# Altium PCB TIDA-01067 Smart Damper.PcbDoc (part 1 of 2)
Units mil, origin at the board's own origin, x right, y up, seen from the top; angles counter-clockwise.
Board outline 4000 x 3450 mil, 4 copper layers (Top Layer, Signal Layer 1, Signal Layer 2, Bottom Layer), stack 63 mil thick; 101 components, 44 nets, 285 pads, 617 vias.
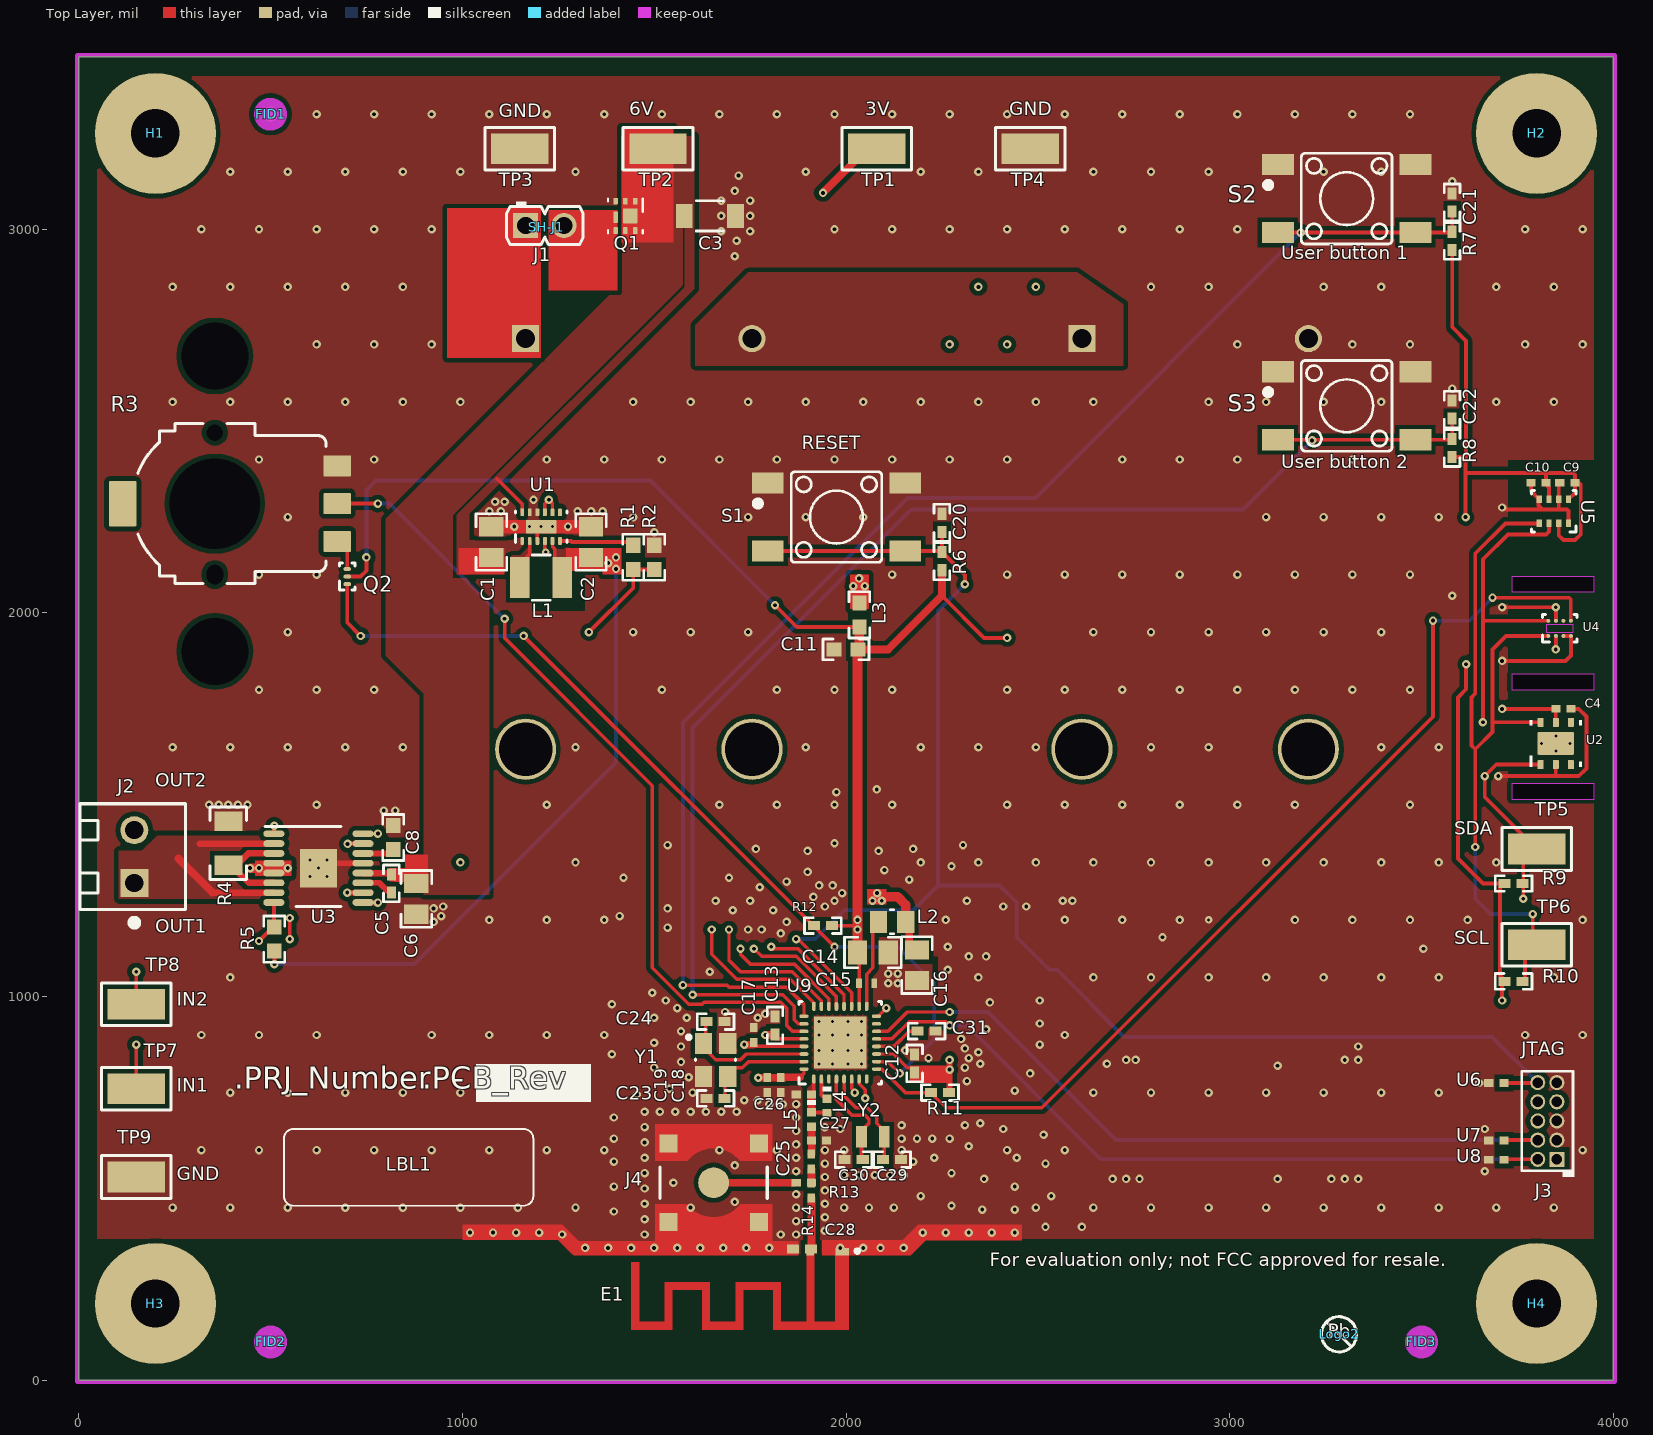
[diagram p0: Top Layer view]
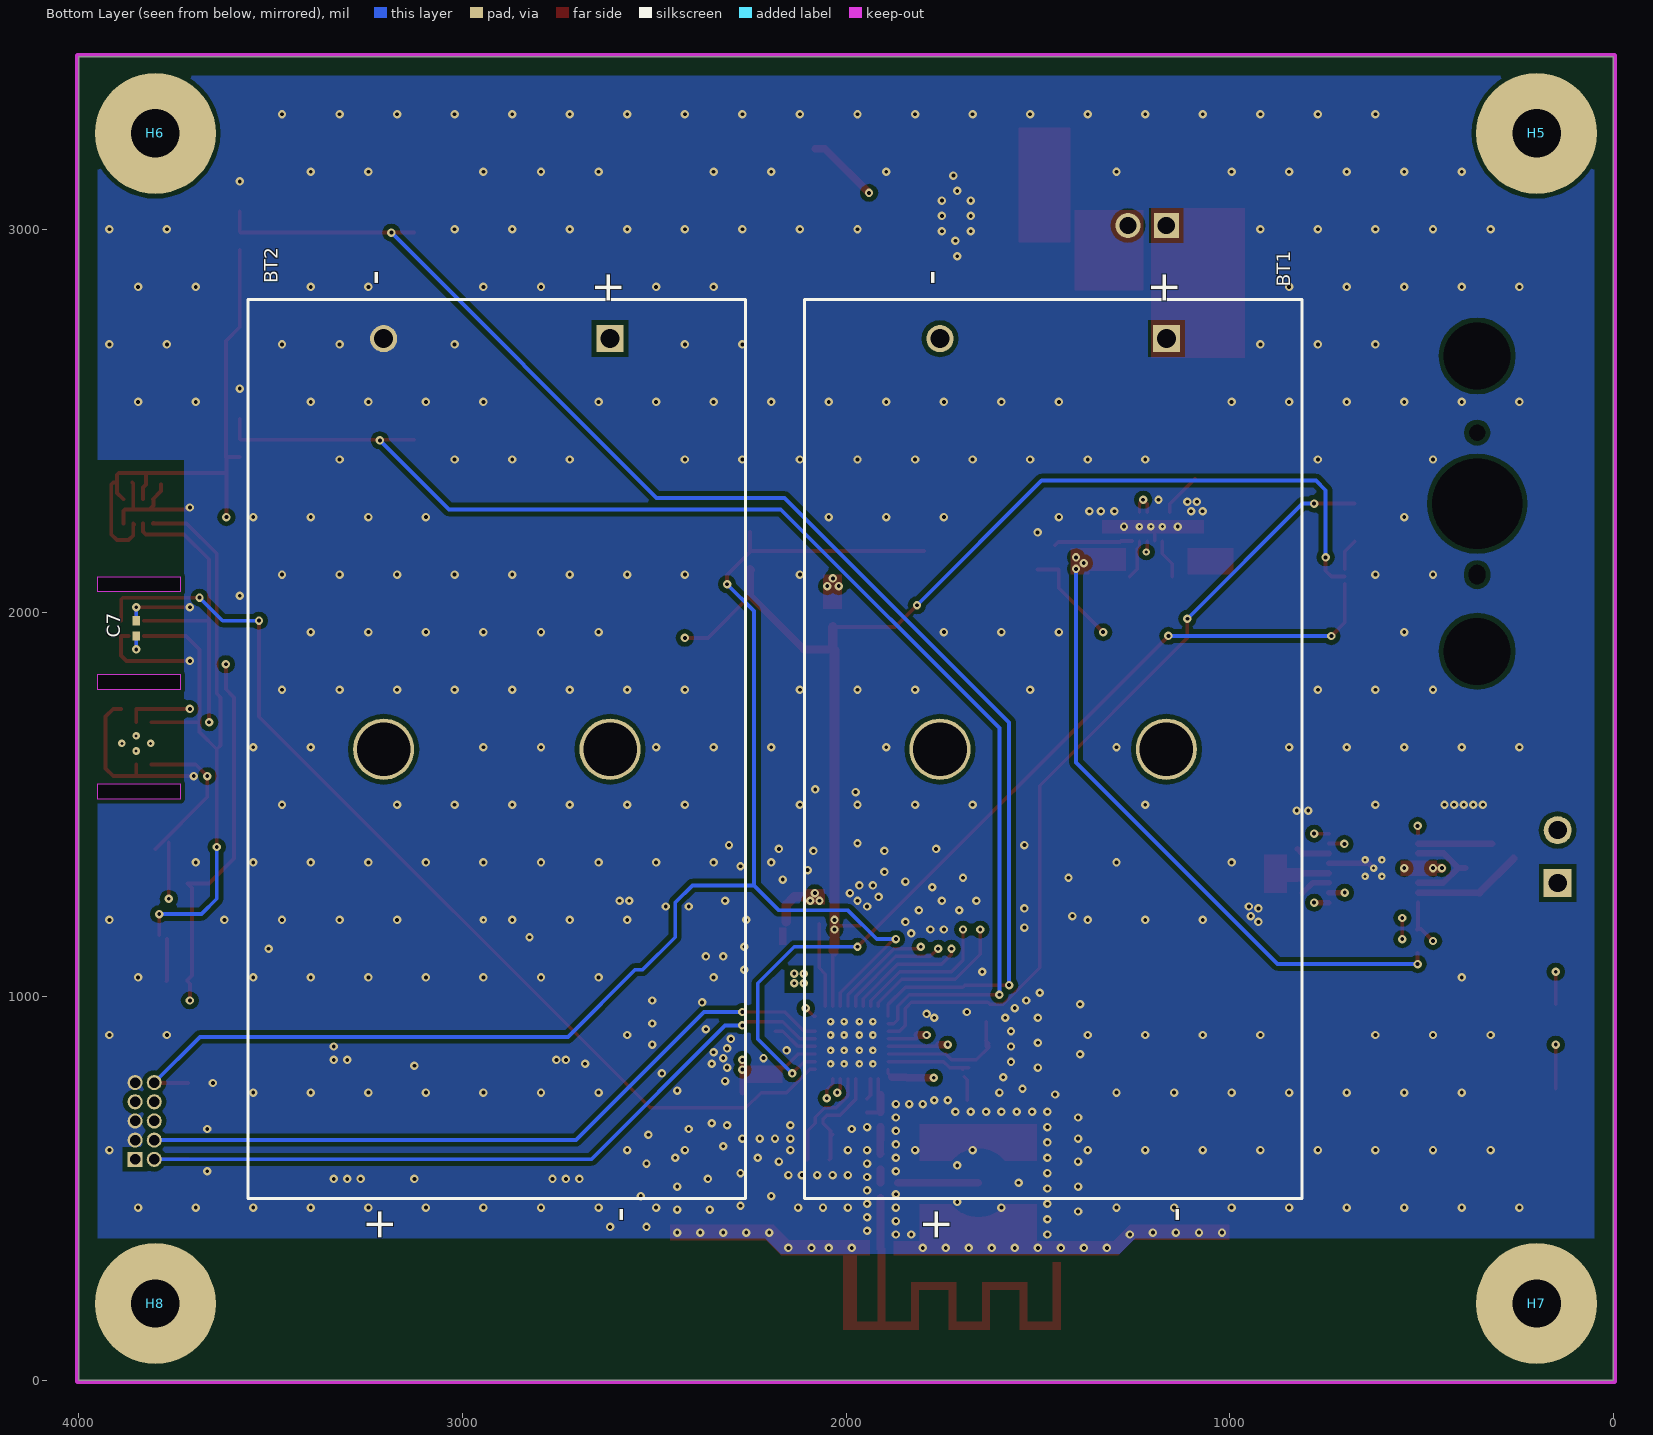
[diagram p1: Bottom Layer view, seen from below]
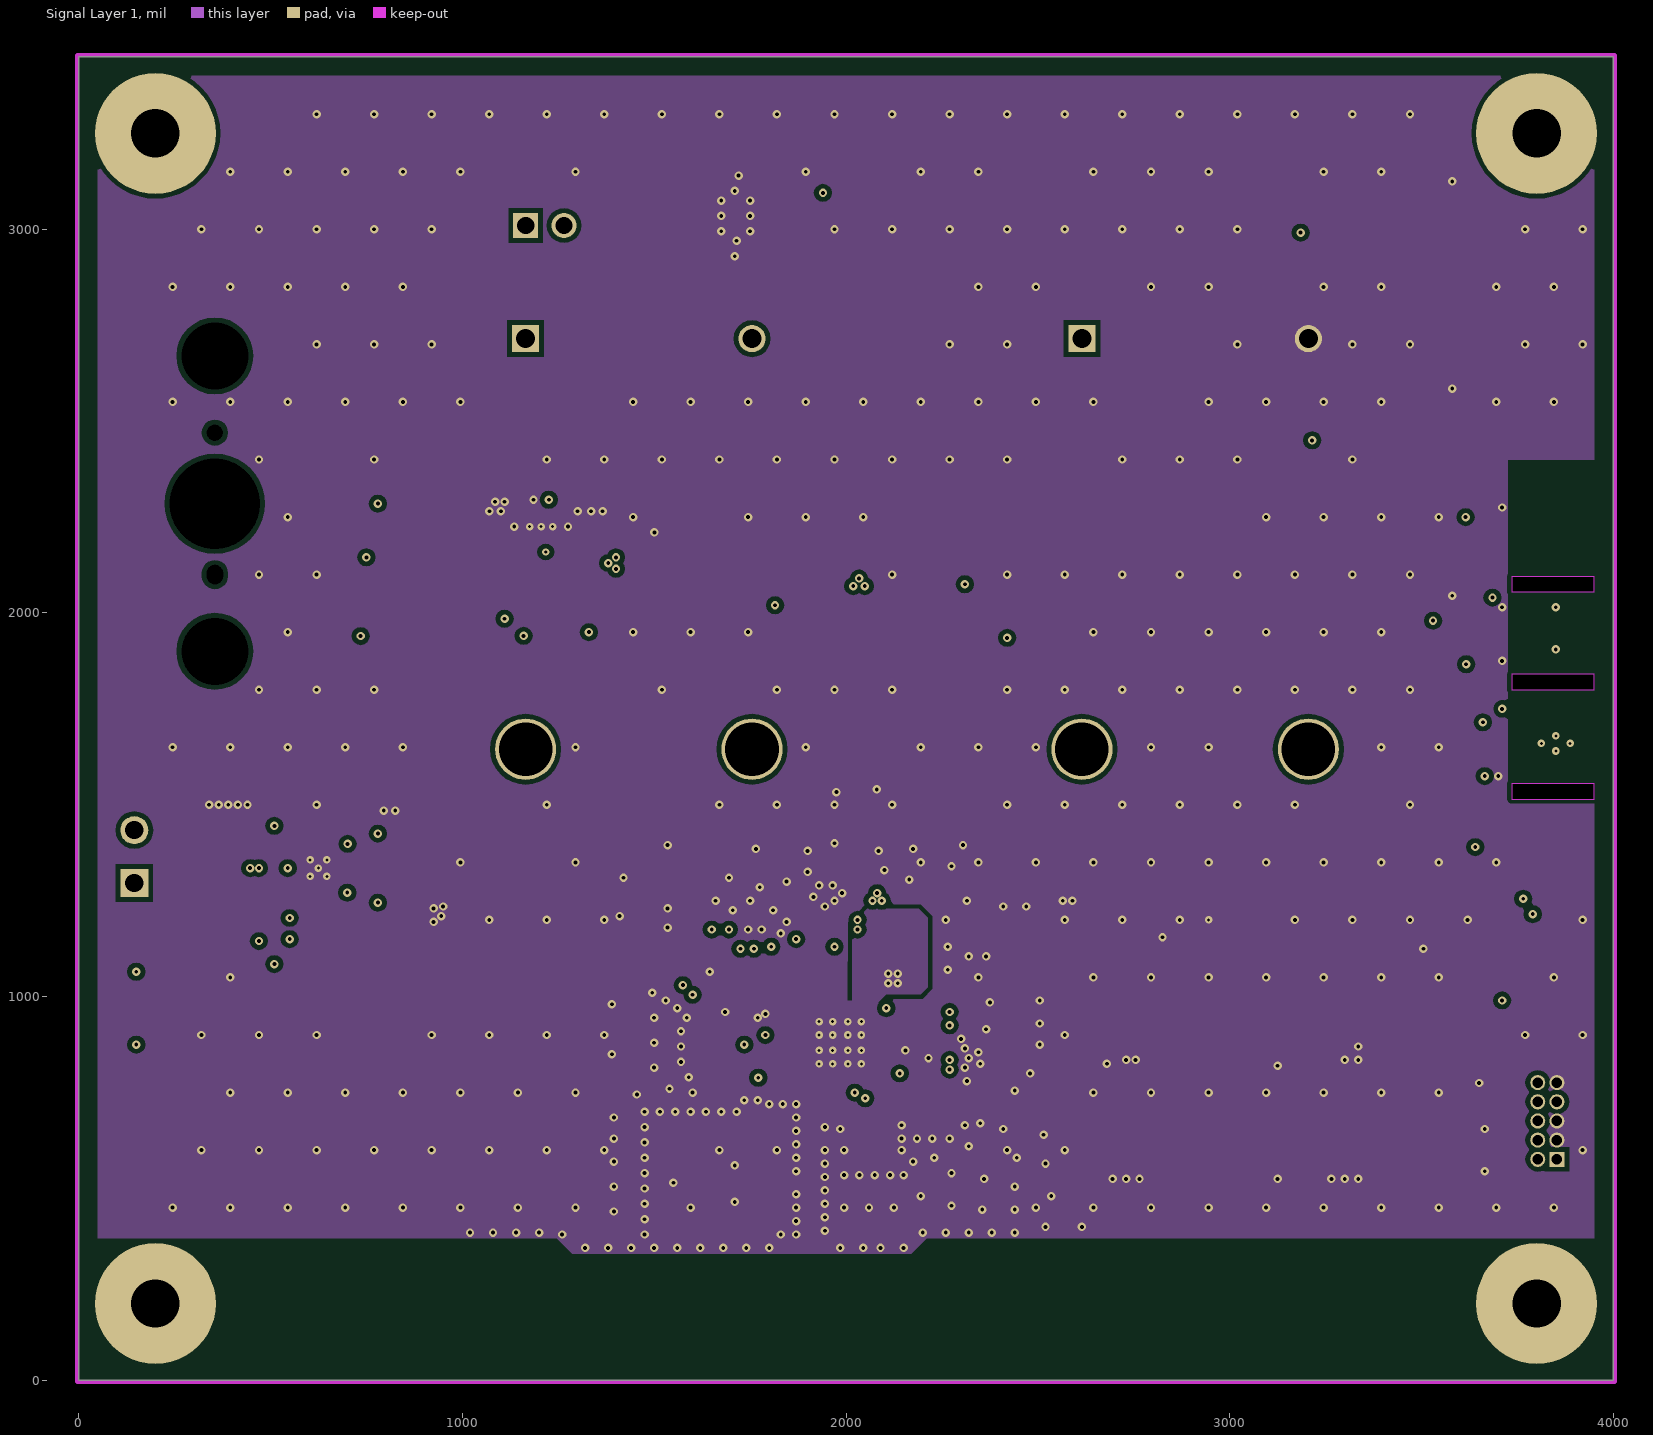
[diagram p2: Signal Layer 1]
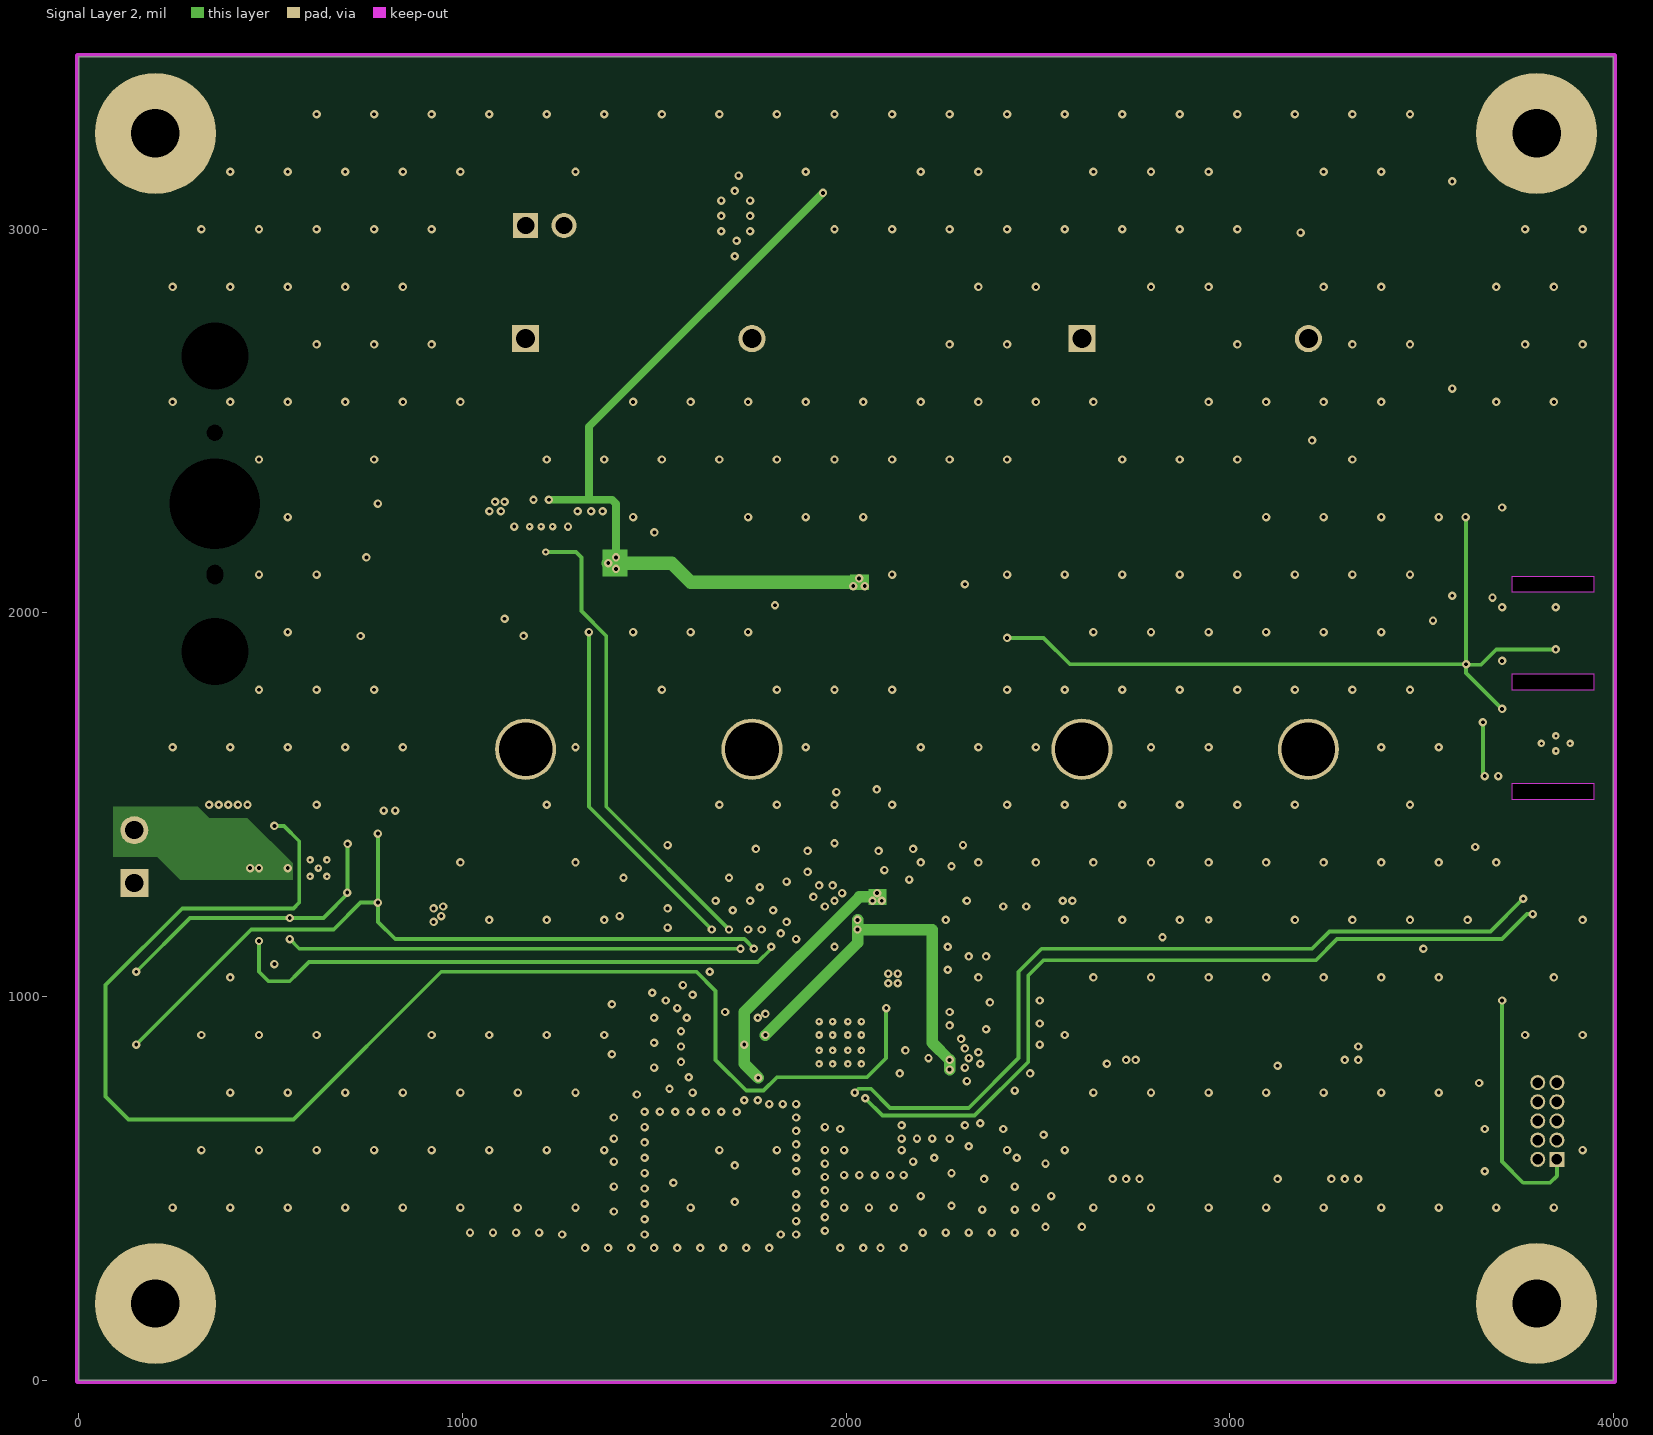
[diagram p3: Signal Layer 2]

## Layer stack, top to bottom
Top Solder: solder mask 0.4, Solder Resist, Dk 3.5
Top Layer: signal copper 1.4
Dielectric1: core 6.9, FR-4 High TG, Dk 4.2
Signal Layer 1: signal copper 0.7
Dielectric 2: prepreg 45, FR-4 High TG, Dk 4.2
Signal Layer 2: signal copper 0.7
Dielectric 3: core 6.9, FR-4 High TG, Dk 4.2
Bottom Layer: signal copper 1.4
Bottom Solder: solder mask 0.4, Solder Resist, Dk 3.5

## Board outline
0,0 0,3450 4000,3450 4000,0
cut-out: 3735,2095 3735,2055 3950,2055 3950,2095
cut-out: 3735,1840 3735,1800 3950,1800 3950,1840
cut-out: 3735,1555 3735,1515 3950,1515 3950,1555

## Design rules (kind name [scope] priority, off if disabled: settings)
AcuteAngle [All] p1: minimum=4.50000000000000E+0001 checktracksonly=FALSE
AssemblyTestPointUsage [All] p1: valid=2
Clearance Clearance_Keepouts [((IsTrack Or IsArc) And Not InPoly) And IsFree and IsKeepOut vs ((IsTrack Or IsArc) And Not InPoly) And IsFree and IsKeepOut] p1: gap=0
Clearance Clearance_Poly [InPolygon] p2: gap=12
Clearance [All] p3: gap=7.87
ComponentClearance ComponentClearance_RF [InComponent('C33') OR InComponent('E1') OR InComponent('R15') OR InComponent('R14')] p1: gap=0 collisioncheckmode=3 verticalgap=0 showdistances=FALSE
ComponentClearance ComponentClearance_MountingHoles_FiducialMarks [InComponentClass('Mounting Holes') vs InComponentClass('FiducialMark')] p2: gap=50 collisioncheckmode=3 verticalgap=10 showdistances=FALSE
ComponentClearance ComponentClearance_Shunt [InComponentClass('Header') vs InComponentClass('Shunt')] p3: gap=0 collisioncheckmode=3 verticalgap=0 showdistances=FALSE
ComponentClearance ComponentClearance_Logo [InComponentClass('Logo')] p4: gap=0 collisioncheckmode=3 verticalgap=0 showdistances=FALSE
ComponentClearance ComponentClearance_ScrewToNut [(HasFootprint('NY PMS 440 0025 PH')) vs (HasFootprint('Keystone_1902E'))] p5: gap=5 collisioncheckmode=3 verticalgap=10 showdistances=FALSE
ComponentClearance ComponentClearance_MountingHoles [InComponentClass('Mounting Holes')] p6: gap=50 collisioncheckmode=3 verticalgap=100000 showdistances=FALSE
ComponentClearance ComponentClearance_SmallPassives [HasFootprint('0201*') or HasFootprint('0402*') or HasFootprint('0508') or HasFootprint('0603*') or HasFootprint('0612') or HasFootprint('0805*') or HasFootprint('0815*') or HasFootprint('0830*') or HasFootprint('1206*') or HasFootprint('1210*') or HasFootprint('1808*') or HasFootprint('1812*') or HasFootprint('1825*') or HasFootprint('2010*') or HasFootprint('2220*') or HasFootprint('2225*') or HasFootprint('2512*') or HasFootprint('2728*') or HasFootprint('3518*') vs HasFootprint('0201*') or HasFootprint('0402*') or HasFootprint('0508') or HasFootprint('0603*') or HasFootprint('0612') or HasFootprint('0805*') or HasFootprint('0815*') or HasFootprint('0830*') or HasFootprint('1206*') or HasFootprint('1210*') or HasFootprint('1808*') or HasFootprint('1812*') or HasFootprint('1825*') or HasFootprint('2010*') or HasFootprint('2220*') or HasFootprint('2225*') or HasFootprint('2512*') or HasFootprint('2728*') or HasFootprint('3518*')] p7: gap=10 collisioncheckmode=3 verticalgap=10 showdistances=FALSE
ComponentClearance ComponentClearance_THtoSMT [IsThruComponent vs IsSMTComponent] p8: gap=40 collisioncheckmode=3 verticalgap=30 showdistances=FALSE
ComponentClearance ComponentClearance_THtoTH [IsThruComponent vs IsThruComponent] p9: gap=30 collisioncheckmode=3 verticalgap=30 showdistances=FALSE
ComponentClearance [All] p10: gap=15 collisioncheckmode=3 verticalgap=10 showdistances=FALSE
DiffPairsRouting [All] p1: maxlimit=100 minlimit=10 mostfreqgap=10 toplayer_minwidth=15 toplayer_maxwidth=15 toplayer_prefwidth=15 midlayer1_minwidth=15 midlayer1_maxwidth=15 midlayer1_prefwidth=15 midlayer2_minwidth=15 midlayer2_maxwidth=15 midlayer2_prefwidth=15 bottomlayer_minwidth=15 bottomlayer_maxwidth=15 bottomlayer_prefwidth=15 maxuncoupledlength=1000
FabricationTestPointUsage TestPointUsage [All] p1: valid=2 allowmultiple=FALSE
FabricationTestpoint Testpoint [All] p1: side=3 testpointundercomponent=TRUE minsize=40 maxsize=100 preferedsize=60 minholesize=0 maxholesize=40 preferedholesize=32 testpointgrid=1 allowsidetop=TRUE allowsidebottom=TRUE usegrid=TRUE gridtolerance=0.01
FanoutControl Fanout_LCC [IsLCC] p1: bgadir=Out bgaviamode=Centered fanoutstyle=Auto fanoutdirection=Alternating viagrid=1 // Fanout_LCC (Default Rule)
FanoutControl Fanout_BGA [IsBGA] p2: bgadir=Out bgaviamode=Centered fanoutstyle=Auto fanoutdirection=Alternating viagrid=1 // Fanout_BGA (Default Rule)
FanoutControl Fanout_Default [All] p4: bgadir=Out bgaviamode=Centered fanoutstyle=Auto fanoutdirection=Alternating viagrid=1 // Fanout_Default (Default Rule)
FanoutControl Fanout_Small [(CompPinCount < 5)] p5: bgadir=Out bgaviamode=Centered fanoutstyle=Auto fanoutdirection=OutThenIn viagrid=1 // Fanout_Small (Default Rule)
Height [All] p1: minheight=0 maxheight=1100 prefheight=500
HoleSize [All] p1: absolutevalues=TRUE maxlimit=251 minlimit=7.87 maxpercent=80.000 minpercent=20.000
MinimumAnnularRing MinimumAnnularRing_ThermalPadVias [IsVia and InAnyComponent] p1: minimumring=5.91
MinimumAnnularRing [All] p2: minimumring=5.5
MinimumSolderMaskSliver MinimumSolderMaskSliver_Logo [InComponentClass('Logo') vs InComponentClass('Logo')] p1: minsoldermaskwidth=0.7
MinimumSolderMaskSliver [All] p2: minsoldermaskwidth=3.94
PlaneConnect [All] p1: planeconnectstyle=Relief reliefexpansion=10 reliefentries=4 reliefconductorwidth=10 reliefairgap=10
PolygonConnect [All] p1: connectstyle=Direct reliefconductorwidth=10 reliefentries=4 polygonreliefangle="90 Angle" airgapwidth=10
RoutingVias ThermalPadVias [IsVia and InAnyComponent] p1: holewidth=7.87 width=19.68 viastyle="Through Hole" minholewidth=7.87 minwidth=19.68 maxholewidth=12.99 maxwidth=23.62
RoutingVias [All] p2: holewidth=10 width=34 viastyle="Through Hole" minholewidth=7.87 minwidth=19 maxholewidth=40 maxwidth=65
SilkToBoardRegionClearance [Not ((IsComment or IsDesignator) And (Hide <> 'False')) and not InRegion(1000,500,4000,800)] p1 off:
SilkToSilkClearance SilkToSilkClearance_Pb-FreeLogo [(HasFootprint('Pb-Free_Overlay_Medium') OR HasFootprint('Pb-Free_Overlay_Small')) vs (HasFootprint('Pb-Free_Overlay_Medium') OR HasFootprint('Pb-Free_Overlay_Small'))] p1: silktosilkclearance=0
SilkToSilkClearance [All] p2: silktosilkclearance=3
SilkToSolderMaskClearance SilkToComponentPadClearance [IsPad and InAnycomponent] p1: minsilkscreentomaskgap=3 clearancetoexposedcopper=TRUE
SilkToSolderMaskClearance "Silk to Solder Mask Opening" [All] p2: minsilkscreentomaskgap=3 clearancetoexposedcopper=FALSE
SolderMaskExpansion [All] p1: expansion=1.97
Width [All] p1: maxlimit=100 minlimit=7.8 preferedwidth=10 checkconnectedcopper=TRUE
14 further rules are at their usual default settings.

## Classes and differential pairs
component class "Mounting Holes": H1 H2 H3 H4
component class "TIDA-01067 Smart Damper_Hardware": FID1 FID2 FID3 H1 H2 H3 H4 H5 H6 H7 H8 LBL1 Logo2 Logo3 SH-J1 ZZ1 ZZ2 ZZ3 ZZ4
component class FiducialMark: FID1 FID2 FID3
component class AssemblyNote: ZZ1 ZZ2 ZZ3 ZZ4
component class Label: LBL1
component class Header: J1 J3
component class "TIDA-01067 Smart Damper_Sheet1": BT1 BT2 C1 C2 C3 C4 C5 C6 C7 C8 C9 C10 J1 J2 L1 Q1 Q2 R1 R2 R3 R4 R5 TP1 TP2 TP3 TP4 U1 U2 U3 U4 U5
component class "TIDA-01067 Smart Damper_Sheet2": C11 C12 C13 C14 C15 C16 C17 C18 C19 C20 C21 C22 C23 C24 C25 C26 C27 C28 C29 C30 C31 E1 J3 J4 L2 L3 L4 L5 R6 R7 R8 R9 R10 R11 R12 R13 R14 S1 S2 S3 TP5 TP6 TP7 TP8 TP9 U6 U7 U8 U9 Y1 Y2
component class Shunt: SH-J1

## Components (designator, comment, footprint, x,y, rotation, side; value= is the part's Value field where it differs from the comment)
BT1 "2462" Keystone_2462 1460,2180 r270 bottom locked
BT2 "2462" Keystone_2462 2910,2180 r270 bottom locked
C1 "EMK212BB7106MG-T" 0805_HV 1075.45,2185 r270 top
C2 "EMK212BB7106MG-T" 0805_HV 1335.45,2185 r270 top
C3 "C3216X5R1A107M160AC" 1206_190 1645,3035 r180 top
C4 "GRM155R71A104KA01D" 0402L 3870,1750 r180 top
C5 "C1005X7R1C103K050BA" 0402 815,1295 r90 top
C6 "EMK212BB7106MG-T" 0805_HV 880,1255 r90 top
C7 "GRM155R71A104KA01D" 0402L 3850,1960 r270 bottom
C8 "C0603C225K9PACTU" 0603 820,1415 r90 top
C9 "GRM155R71A104KA01D" 0402L 3880,2340 r0 top
C10 "GRM155R71A104KA01D" 0402L 3805,2340 r0 top
C11 "C1608X5R1A106M080AC" 0603 2000,1905 r180 top
C12 "GRM155R71A104KA01D" 0402 2179,826 r270 top
C13 "GRM155R71A104KA01D" 0402 1815,925 r270 top
C14 "GRM21BR71A106KE51L" 0805_HV 2070,1115 r0 top
C15 "GRM155R71A104KA01D" 0402S 2053.9,1035 r180 top
C16 "GRM21BR71A106KE51L" 0805_HV 2185,1082 r270 top
C17 "GRM155R71A104KA01D" 0402L 1760,900 r270 top
C18 "GRM155R71A104KA01D" 0402L 1830,770 r90 top
C19 "885012205037" 0402L 1795,770 r270 top
C20 "C1005X7R1H222K" 0402 2250,2235 r270 top
C21 "C1005X7R1H222K" 0402 3580,3070 r270 top
C22 "C1005X7R1H222K" 0402 3580,2530 r270 top
C23 "GRM1555C1H120JA01D" 0402 1660,735 r0 top
C24 "GRM1555C1H120JA01D" 0402 1660,935 r180 top
C25 "GRM1555C1H120JA01D" 0402L 1910,570 r90 top
C26 "GRM1555C1H1R2CA01D" 0402L 1890,745 r180 top
C27 "GRM1555C1H1R2CA01D" 0402L 1930,625 r0 top
C28 "GRM1555C1H1R2CA01D" 0402 1885,342 r0 top
C29 "GRM1555C1H120JA01D" 0402 2120,575 r180 top
C30 "GRM1555C1H120JA01D" 0402 2020,575 r180 top
C31 "GRM155R61A105KE15D" 0402 2210,910 r180 top
E1 "ANTENNA_IIFA" ANTENNA_IIFA 1990,345 r180 top net-tie
FID1 "Fiducial" Fiducial10-20 500,3300 r0 top
FID2 "Fiducial" Fiducial10-20 500,100 r0 top
FID3 "Fiducial" Fiducial10-20 3500,100 r0 top
H1 "NY PMS 440 0025 PH" "NY PMS 440 0025 PH" 200,3250 r0 top locked
H2 "NY PMS 440 0025 PH" "NY PMS 440 0025 PH" 3800,3250 r0 top locked
H3 "NY PMS 440 0025 PH" "NY PMS 440 0025 PH" 200,200 r0 top locked
H4 "NY PMS 440 0025 PH" "NY PMS 440 0025 PH" 3800,200 r0 top locked
H5 "1902E" Keystone_1902E 200,3250 r180 bottom locked
H6 "1902E" Keystone_1902E 3800,3250 r180 bottom locked
H7 "1902E" Keystone_1902E 200,200 r180 bottom locked
H8 "1902E" Keystone_1902E 3800,200 r180 bottom locked
J1 "61300211121" WURTH_61300211121 1215,3010 r0 top
J2 "OSTTE020161" On-Shore_OSTTE020161 145,1365 r90 top
J3 "GRPB052VWVN-RC" CONN_GRPB052VWVN-RC 3828,676 r90 top
J4 "CONSMA001-SMD-G" Linx_CONSMA001-SMD-G 1655,515 r90 top
L1 "CBC3225T4R7MR" CBC3225 1205.45,2092 r0 top
L2 "CKS2125100M-T" 0805_145 2120,1195 r0 top
L3 "BLM18HE152SN1D" 0603 2035,1995 r270 top
L4 "LQG15HS15NJ02D" IND_LQG15H 1950,715 r270 top
L5 "LQG15HS2N0S02D" IND_LQG15H 1910,680 r270 top
LBL1 "Size: 0.65\" x 0.20 \"" Label_650x200 860,555 r0 top
Logo2 "Pb-Free Symbol" Pb-Free_Overlay_Small 3285,120 r0 top
Logo3 "FCC disclaimer" FCC_disclaimer 1010,-460 r270 top
Q1 "CSD25310Q2" TRANS_NexFET_Q2 1425,3035 r270 top
Q2 "CSD23285F5" YJK0003A 700,2095 r90 top
R1 "RC0603FR-0738K3L" 0603 1445.45,2145 r90 top
R2 "ERJ-3EKF3002V" 0603 1500.45,2145 r90 top
R3 "EVW-AE4001B14" Panasonic_EVW-AE4001B14 355,2285 r180 top
R4 "CSR1206FKR100" 1206 390,1400 r270 top
R5 "ERJ-3EKF1001V" 0603 510,1150 r270 top
R6 "CRCW040247K5FKED" 0402 2250,2135 r270 top
R7 "CRCW040247K5FKED" 0402 3580,2970 r270 top
R8 "CRCW040247K5FKED" 0402 3580,2430 r270 top
R9 "CRCW040210K0FKED" 0402 3740,1295 r180 top
R10 "CRCW040210K0FKED" 0402 3740,1040 r180 top
R11 "CRCW040210K0FKED" 0402 2245,750 r0 top
R12 "CRCW040210K0FKED" 0402 1940,1185 r0 top
R13 "CRCW04021K00JNED" 0402L 1890,515 r180 top
R14 "ERJ-2GE0R00X" 0402L 1910,495 r270 top
S1 "4-1437565-1" SW_FSM4JSMA 1975,2250 r90 top
S2 "4-1437565-1" SW_FSM4JSMA 3305,3080 r90 top
S3 "4-1437565-1" SW_FSM4JSMA 3305,2540 r90 top
SH-J1 "969102-0000-DA" SNT-100-BK-G 1220,3005 r180 top
TP1 "TESTPOINT" Keystone_5019 2080,3210 r0 top
TP2 "TESTPOINT" Keystone_5019 1510,3210 r0 top
TP3 "TESTPOINT" Keystone_5019 1150,3210 r0 top
TP4 "TESTPOINT" Keystone_5019 2480,3210 r0 top
TP5 "TESTPOINT" Keystone_5019 3800,1385 r0 top
TP6 "TESTPOINT" Keystone_5019 3800,1135 r0 top
TP7 "TESTPOINT" Keystone_5019 150,760 r0 top
TP8 "TESTPOINT" Keystone_5019 150,980 r180 top
TP9 "TESTPOINT" Keystone_5019 150,530 r0 top
U1 "TPS62745DSSR" DSS0012A 1205.45,2225 r90 top
U2 "HDC1080DMBR" DMB0006A 3850,1660 r90 top
U3 "DRV8833PWPR" PWP0016C_N 625,1335 r0 top
U4 "HDC1010YPAR" YPA0008AGAE 3860,1960 r90 top
U5 "BMP280" LGA8-2X2_5MM_0_65 3845,2265 r180 top
U6 "TPD1E10B06DPYR" DPY0002A 3695,775 r180 top
U7 "TPD1E10B06DPYR" DPY0002A 3695,625 r180 top
U8 "TPD1E10B06DPYR" DPY0002A 3695,575 r180 top
U9 "CC2650F128RHBR" RHB0032E 1985,880 r90 top locked
Y1 "TSX-3225 24.0000MF20G-AC3" EPSON_TSX-3225 1660,835 r0 top
Y2 "FC-12M 32.7680KA-A3" Epson_FC-12M 2070,635 r0 top
ZZ1 "This Assembly Note is for PCB labels only" AssemblyNoteLabel 185,3915 r0 top
ZZ2 "These assemblies are ESD sensitive, ESD precautions shall be observed." AssemblyNote 185,3829.11 r0 top
ZZ3 "These assemblies must be clean and free from flux and all contaminants. Use of no clean flux is not acceptable." AssemblyNote 185,3740.56 r0 top
ZZ4 "These assemblies must comply with workmanship standards IPC-A-610 Class 2, unless otherwise specified." AssemblyNote 185,3652 r0 top

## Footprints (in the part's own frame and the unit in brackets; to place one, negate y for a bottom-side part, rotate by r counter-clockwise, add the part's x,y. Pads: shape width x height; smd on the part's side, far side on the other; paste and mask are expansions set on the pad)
0402 [mm] "0402 from SM-752 data"
  rect 0.8x0.6 smd: 1(-0.6,0) 2(0.6,0)
  silkscreen extent -1.22,-0.52 1.22,0.52, body extent -0.55,-0.3 0.55,0.3, height 0.6
0402L [mm] "0402 from SM-752 data"
  rect 0.6x0.5 smd: 1(-0.5,0) 2(0.5,0)
  body extent -0.55,-0.3 0.55,0.3, height 0.6
0402S [mil] "Based on C0402S footprint from PADS legacy"
  rect 15x24 smd: 1(-20,0) 2(20,0)
  body extent -22,-12 22,12, height 24
0603 [mm] "0603 from SM-752 data"
  rect 1x0.95 smd: 1(-0.8,0) 2(0.8,0)
  silkscreen extent -1.52,-0.69 1.52,0.69, body extent -0.87,-0.47 0.87,0.47, height 1
0805_145 [mm] "0805 / 1.45mm height"
  rect 1.15x1.45 smd: 1(-0.9,0) 2(0.9,0)
  silkscreen extent -0.1,-0.8 0.1,0.8, body extent -1.1,-0.72 1.1,0.72, height 1.45
0805_HV [mil] "0805 with 30mil clearance between pads"
  rect 50x63 smd: 1(-40,0) 2(40,0)
  silkscreen extent -74,-40 74,40, body extent -43,-29 43,29, height 57
1206 [mm] "1206 from SM-752 data"
  rect 1.3x1.85 smd: 1(-1.45,0) 2(1.45,0)
  silkscreen extent -2.4,-1.21 2.4,1.21, body extent -1.7,-0.9 1.7,0.9, height 1.35
1206_190 [mm] "1206_190"
  rect 1.1x1.6 smd: 1(-1.7,0) 2(1.7,0)
  silkscreen extent -0.9,-1 0.9,1, body extent -1.75,-0.95 1.75,0.95, height 1.9
ANTENNA_IIFA [mm] "PCB Antenna, 2-Leads"
  rect 0.9x0.5 smd paste-1 mask-1: 1(0,0.25)
  rect 0.5x0.5 smd paste-1 mask-1: 2(2.1,0.25)
  Top Layer region: -0.45,0 -0.45,5.4 4.55,5.4 4.55,2.76 6.55,2.76 6.55,5.4 9.25,5.4 9.25,2.76 11.25,2.76 11.25,5.4 13.95,5.4 13.95,0.96 13.45,0.96 13.45,4.9 11.75,4.9 11.75,2.26 8.75,2.26 8.75,4.9 7.05,4.9 7.05,2.26 4.05,2.26 4.05,4.9 2.35,4.9 2.35,0 1.85,0 1.85,4.9 0.45,4.9 0.45,0
  silkscreen extent -1.1,0.11 -0.9,0.31
AssemblyNote [mil] "Assembly Note"
AssemblyNoteLabel [mil] "Assembly Note for PCB Labels"
CBC3225 [mm] "TAIYO YUDEN, IPC nominal footprint."
  rect 1.29x2.72 smd: 1(-1.405,0) 2(1.405,0)
  silkscreen extent -0.6,-1.5 0.6,1.5, body extent -1.7,-1.35 1.7,1.35, height 2.7
CONN_GRPB052VWVN-RC [mm] "SULLINS"
  rect 1x1 hole 0.7 mask+0.08: 1(-2.54,-0.635)
  round 1 hole 0.7 mask+0.08: 2(-2.54,0.635) 3(-1.27,-0.635) 4(-1.27,0.635) 5(0,-0.635) 6(0,0.635) 7(1.27,-0.635) 8(1.27,0.635) 9(2.54,-0.635) 10(2.54,0.635)
  silkscreen extent -3.7,-1.8 3.3,1.7, body extent -3.17,-1.7 3.17,1.7, height 4
DMB0006A [mm] "TI"
  rrect25% 0.6x0.4 smd: 1(-1.4,1) 2(-1.4,0) 3(-1.4,-1) 4(1.4,-1) 5(1.4,0) 6(1.4,1)
  rrect9% 1.38x1.06 on Top Paste: 7(0,0.63) 7(0,-0.63)
  rrect7% 1.5x2.4 smd paste-0.75: 7(0,0)
  silkscreen extent -1.55,-1.75 1.55,1.75, body extent -1.5,-1.5 1.5,1.5, height 0.81
DPY0002A [mm] "R-PX2SON-N2"
  rect 0.6x0.5 smd: 1(-0.5,0) 2(0.5,0)
  body extent -0.55,-0.35 0.55,0.35, height 0.4
DSS0012A [mm] "SON, 12-Leads, Body 2x3mm, Pitch 0.5mm, Thermal Pad 2x0.9mm, TI Recommended"
  rrect40% 0.5x0.25 smd: 1(-0.95,1.25) 2(-0.95,0.75) 3(-0.95,0.25) 4(-0.95,-0.25) 5(-0.95,-0.75) 6(-0.95,-1.25) 7(0.95,-1.25) 8(0.95,-0.75) 9(0.95,-0.25) 10(0.95,0.25) 11(0.95,0.75) 12(0.95,1.25)
  rrect11% 0.9x0.9 on Top Paste: 13(0,0.55) 13(0,-0.55)
  rrect11% 0.9x2 smd paste-0.45: 13(0,0)
  silkscreen extent -1.05,-1.7 1.05,1.7, body extent -1,-1.5 1,1.5, height 0.81
Epson_FC-12M [mm] "Epson"
  rect 0.7x1.4 smd: 1(-0.75,0) 2(0.75,0)
  body extent -1.05,-0.63 1.05,0.63, height 0.6
EPSON_TSX-3225 [mm] "SMD, 4-Leads, Body 2.65x3.35mm, Height 0.6mm"
  rect 1.15x1.4 smd: 1(-0.8,1.1) 2(-0.8,-1.1) 3(0.8,-1.1) 4(0.8,1.1)
  silkscreen extent -1.9,-0.05 1.33,1.62, body extent -1.33,-1.68 1.33,1.68, height 0.61
FCC_disclaimer [mil]
Fiducial10-20 [mm]
  round 1 smd mask+0.5: 1(0,0)
  Top Layer keep-out circle w1.178: c0,0 r0.5
IND_LQG15H [mm] "MuRata"
  rect 0.55x0.6 smd: 1(-0.475,0) 2(0.475,0)
  silkscreen extent -1.3,-0.3 -0.95,0.3, body extent -0.52,-0.27 0.52,0.27, height 0.55
Keystone_1902E [mil] "Hex Standoff, 4-40 threaded, nylon"
  round 1 on Mech4: 0(0,0)
  body extent -145,-126 146,126, height 1001
Keystone_2462 [mm] "2x AA Battery Holder, Through-hole mount"
  rect 1.8x1.8 hole 1.27: 1(-13.59,7.495)
  round 1.8 hole 1.27: 2(-13.59,-7.495)
  round 4.05 hole 3.55: 3(13.59,-7.495) 4(13.59,7.495)
  silkscreen extent -16.18,-16.46 43.33,16.46, body extent -16.31,-16.46 43.4,16.46, height 16
Keystone_5019 [mm] "Test Point, Miniature, SMT"
  rect 3.8x2.03 smd: 1(0,0)
  silkscreen extent -2.31,-1.42 2.31,1.42, body extent -1.9,-1.02 1.9,1.02, height 2.29
Label_650x200 [mil] "Thermal Transfer Label"
  silkscreen extent -325,-100 325,100, body extent -325,-100 325,100, height 1
LGA8-2X2_5MM_0_65 [mm] "LGA, 8-Leads, Body 2x2.5mm, Pitch 0.65mm"
  rect 0.35x0.5 smd: 1(-0.975,0.8) 2(-0.325,0.8) 3(0.325,0.8) 4(0.975,0.8) 5(0.975,-0.8) 6(0.325,-0.8) 7(-0.325,-0.8) 8(-0.975,-0.8)
  silkscreen extent -1.47,-1.36 1.47,1.36, body extent -1.3,-1.05 1.3,1.05, height 1.01
Linx_CONSMA001-SMD-G [mm] "SMD, 5-Leads, Body 7x7mm, Height 10.5mm"
  round 2.05 smd: 1(0,0)
  rect 1.2x1.2 smd: 2(-2.6,-3) 3(2.6,-3) 4(2.6,3) 5(-2.6,3)
  Top Layer region: -3.88,-3.88 -1.44,-3.88 -1.44,-1.761 -1.448,-1.761 -2.062,-0.974 -2.28,0 -2.062,0.974 -1.448,1.761 -1.448,1.761 -1.44,1.761 -1.44,3.88 -3.88,3.88
  Top Layer region: 3.88,-3.88 1.44,-3.88 1.44,-1.761 1.448,-1.761 2.062,-0.974 2.28,0 2.062,0.974 1.448,1.761 1.448,1.761 1.44,1.761 1.44,3.88 3.88,3.88
  silkscreen extent -1.04,-3.55 1.04,3.55, body extent -3.55,-3.55 3.55,3.55, height 10.5
"NY PMS 440 0025 PH" [mm] "4-40 nylon screw and mounting hole"
  round 8 hole 3.2: 1(0,0)
  body extent -3.3,-3.3 3.3,3.3, height 2.69
On-Shore_OSTTE020161 [mm] "Term Blk 2x1"
  rect 1.85x1.85 hole 1.2: 1(-1.75,0)
  round 1.85 hole 1.2: 2(1.75,0)
  silkscreen extent -4.47,-3.4 3.5,3.6, body extent -3.5,-3.4 3.5,3.6, height 8.4
Panasonic_EVW-AE4001B14 [mm] "SMD, 4-Leads, Body 10.6x12.65mm"
  rrect7% 1.8x1.4 smd: 1(-8.1,2.5) 2(-8.1,0) 3(-8.1,-2.5)
  rrect6% 1.8x3 smd: 4(6.1,0)
  round 0 hole 1.1 slot 1.3 at 90 deg unplated: ""(0,4.7)
  round 0 hole 6 unplated: ""(0,0)
  round 0 hole 1.1 unplated: ""(0,-4.7)
  silkscreen extent -7.35,-5.3 5.1,5.3, body extent -8.7,-5.3 6.7,5.3, height 2.2
Pb-Free_Overlay_Small [mil]
  silkscreen extent -46,-46 46,46
PWP0016C_N [mm] "SOP, 16-Leads, Body 5x4.4mm, Pitch 0.65mm, Thermal Pad 2.56x2.46mm, IPC Medium Density"
  rrect100% 1.4x0.45 smd: 1(-2.95,2.275) 2(-2.95,1.625) 3(-2.95,0.975) 4(-2.95,0.325) 5(-2.95,-0.325) 6(-2.95,-0.975) 7(-2.95,-1.625) 8(-2.95,-2.275) 9(2.95,-2.275) 10(2.95,-1.625) 11(2.95,-0.975) 12(2.95,-0.325) 13(2.95,0.325) 14(2.95,0.975) 15(2.95,1.625) 16(2.95,2.275)
  rrect4% 2.46x2.56 smd: 17(0,0)
  silkscreen extent -3.55,-2.55 1.5,2.75, body extent -3.21,-2.5 3.21,2.5, height 1
RHB0032E [mm] "QFN, 32-Leads, Body 5x5mm, Pitch 0.5mm, Thermal Pad 3.45x3.45mm, TI Recommended"
  oval 0.6x0.24 smd: 1(-2.4,1.75) 2(-2.4,1.25) 3(-2.4,0.75) 4(-2.4,0.25) 5(-2.4,-0.25) 6(-2.4,-0.75) 7(-2.4,-1.25) 8(-2.4,-1.75) 17(2.4,-1.75) 18(2.4,-1.25) 19(2.4,-0.75) 20(2.4,-0.25) 21(2.4,0.25) 22(2.4,0.75) 23(2.4,1.25) 24(2.4,1.75)
  oval 0.24x0.6 smd: 9(-1.75,-2.4) 10(-1.25,-2.4) 11(-0.75,-2.4) 12(-0.25,-2.4) 13(0.25,-2.4) 14(0.75,-2.4) 15(1.25,-2.4) 16(1.75,-2.4) 25(1.75,2.4) 26(1.25,2.4) 27(0.75,2.4) 28(0.25,2.4) 29(-0.25,2.4) 30(-0.75,2.4) 31(-1.25,2.4) 32(-1.75,2.4)
  rect 3.45x3.45 smd paste-1.725: 33(0,0)
  silkscreen extent -2.72,-2.73 2.72,2.73, body extent -2.57,-2.57 2.58,2.58, height 1.01
SNT-100-BK-G [mil] "Samtec STEP model"
  round 1 on Mech3: 0(0,0)
  body extent -100,-50 100,50, height 344
SW_FSM4JSMA [mm] "Alcoswitch"
  rect 1.4x2.1 smd: 1(2.25,4.55) 2(2.25,-4.55) 3(-2.25,4.55) 4(-2.25,-4.55)
  silkscreen extent -3,-3 3,5.4, body extent -3,-5 3,5, height 5.1
TRANS_NexFET_Q2 [mm] "TI recommended land pattern M0167-01"
  rrect33% 0.45x0.3 smd: 1(-0.975,0.65) 2(-0.975,0) 3(-0.975,-0.65) 4(0.975,-0.65) 5(0.975,0) 6(0.975,0.65)
  rrect33% 0.75x0.3 smd paste-0.025: 7(0.095,-0.65)
  rrect11% 1x0.95 smd paste-0.025: 8(0,0.325)
  silkscreen extent -1.15,-1.15 1.15,1.15, body extent -1,-1 1,1, height 0.85
WURTH_61300211121 [mm] "Header, 2.54mm, 2x1, TH"
  rect 1.65x1.65 hole 1.15: 1(-1.27,0)
  round 1.65 hole 1.15: 2(1.27,0)
  silkscreen extent -2.54,-1.27 2.54,1.6, body extent -2.54,-1.27 2.54,1.27, height 8.54
YJK0003A [mm] "SMD, 3-Leads, Body 1.49x0.73mm"
  rrect50% 0.2x0.39 on Top Paste: 1(-0.525,0) 2(0,0) 3(0.525,0)
  rrect80% 0.25x0.49 smd paste-0.15 mask-0.05: 1(-0.5,0) 2(0,0) 3(0.5,0)
  silkscreen extent -0.9,-0.5 0.9,0.5, body extent -0.75,-0.37 0.74,0.36, height 0.35
YPA0008AGAE [mm] "BGA, 8-Leads, Body 2.04x1.59mm, Pitch 0.5mm"
  round 0.263 smd paste-0.14: A1(-0.5,0.75) A2(0.5,0.75) B1(-0.5,0.25) B2(0.5,0.25) C1(-0.5,-0.25) C2(0.5,-0.25) D1(-0.5,-0.75) D2(0.5,-0.75)
  Top Layer keep-out region: -0.25,-0.9 0.25,-0.9 0.25,0.9 -0.25,0.9
  silkscreen extent -0.91,-1.14 0.91,1.14, body extent -0.81,-1.04 0.81,1.04, height 0.68

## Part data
BT1 BT2: "2x AA Battery Holder, Through-hole mount"
C1 C2 C6: "CAP, CERM, 10 µF, 16 V, +/- 20%, X7R, 0805"
C3: "CAP, CERM, 100 µF, 10 V, +/- 20%, X5R, 1206_190"
C4 C7 C9 C10 C12 C13 C15 C17 C18: "CAP, CERM, 0.1 µF, 10 V, +/- 10%, X7R, 0402"
C5: "CAP, CERM, 0.01 µF, 16 V, +/- 10%, X7R, 0402"
C8: "CAP, CERM, 2.2 µF, 6.3 V, +/- 10%, X5R, 0603"
C11: "CAP, CERM, 10 µF, 10 V, +/- 20%, X5R, 0603"
C14 C16: "CAP, CERM, 10 µF, 10 V, +/- 10%, X7R, 0805"
C19: "CAP, CERM, 0.1 µF, 16 V, +/- 10%, X7R, 0402"
C20 C21 C22: "CAP, CERM, 2200 pF, 50 V, +/- 10%, X7R, 0402"
C23 C24 C25 C29 C30: "CAP, CERM, 12 pF, 50 V, +/- 5%, C0G/NP0, 0402"
C26 C27 C28: "CAP, CERM, 1.2 pF, 50 V, +/- 5%, C0G/NP0, 0402"
C31: "CAP, CERM, 1 µF, 10 V, +/- 10%, X5R, 0402"
E1: "PCB Antenna.  There is nothing to buy or mount."
FID1 FID2 FID3: "Fiducial mark.  There is nothing to buy or mount."
H1 H2 H3 H4: "Machine Screw, Round, #4-40 x 1/4, Nylon, Philips panhead"
H5 H6 H7 H8: "Standoff, Hex, 1\"L #4-40 Nylon"
J1: "Header, 2.54 mm, 2x1, Gold, TH"
J2: "Terminal Block, 2x1, 3.5mm, TH"
J3: "Header, 50mil, 5x2, Gold, TH"
J4: "Jack, SMA, PCB, Gold, SMT"
L1: "Inductor, Wirewound, 4.7 µH, 1.01 A, 0.1 ohm, SMD"
L2: "Inductor, Multilayer, Ferrite, 10 µH, 0.11 A, 0.52 ohm, SMD"
L3: "Ferrite Bead, 1500 ohm @ 100 MHz, 0.5 A, 0603"
L4: "Inductor, Multilayer, Air Core, 15 nH, 0.3 A, 0.32 ohm, SMD"
L5: "Inductor, Multilayer, Air Core, 2 nH, 0.3 A, 0.1 ohm, SMD"
LBL1: library part THT-14-423-10, "Thermal Transfer Printable Labels, 0.650\" W x 0.200\" H - 10,000 per roll"
Logo2: library part Pb-Free
Logo3: library part FCC_disclaimer, "FCC_disclaimer"
Q1: "MOSFET, P-CH, -20 V, -20 A, SON 2x2mm"
Q2: "MOSFET, P-CH, -12 V, -3.3 A, YJK0003A (PICOSTAR-3)"
R1: "RES, 38.3 k, 1%, 0.1 W, 0603"
R2: "RES, 30.0 k, 1%, 0.1 W, AEC-Q200 Grade 0, 0603"
R3: "10 mm GS Sensor, SMD"
R4: "RES, 0.1, 1%, 0.5 W, 1206"
R5: "RES, 1.00 k, 1%, 0.1 W, 0603"
R6 R7 R8: "RES, 47.5 k, 1%, 0.063 W, 0402"
R9 R10 R11 R12: "RES, 10.0 k, 1%, 0.063 W, 0402"
R13: "RES, 1.0 k, 5%, 0.063 W, 0402"
R14: "RES, 0, 5%, 0.063 W, 0402"
S1 S2 S3: "Switch, Tactile, SPST-NO, 0.05A, 12V, SMT"
SH-J1: "Shunt, 100mil, Gold plated, Black"
TP1 TP2 TP3 TP4 TP5 TP6 TP7 TP8 TP9: library part 5019, "Test Point, Miniature, SMT"
U1: "Dual-cell Ultra Low IQ Step Down Converter for Low Power Wireless Applications, DSS0012A"
U2: "HDC1080 Low Power, High Accuracy Digital Humidity Sensor with Temperature Sensor, DMB0006A (WSON-6)"
U3: "Dual H-Bridge Motor Driver, PWP0016C"
U4: "Low Power, High Accuracy Digital Humidity Sensor with Temperature Sensor, YPA0008AGAE (DSBGA-8)"
U5: "Digital Pressure Sensor, LGA8-2X2_5MM_0_65"
U6 U7 U8: "ESD in 0402 Package with 10 pF Capacitance and 6 V Breakdown, 1 Channel, -40 to +125 degC, 2-pin X2SON (DPY), Green (RoHS & no Sb/Br)"
U9: "Ultra low-power ARM Cortex M3 2.4 GHz Radio MCU, Multi-Protocol, RSHB032E (VQFN-32)"
Y1: "Crystal, 24 MHz, 9 pF, SMD"
Y2: "Crystal, 32.768kHz, 12.5pF, SMD"
ZZ1: library part AssemblyNoteLabel
ZZ2 ZZ3 ZZ4: library part AssemblyNote

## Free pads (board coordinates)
  round 60 hole 175 unplated: 0(355,1900) 0(355,2670)

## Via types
v1: diameter 22, hole 10, Top Layer to Bottom Layer, tented both sides, 560 vias
v2: diameter 19.68, hole 7.87, Top Layer to Bottom Layer, 29 vias
v3: diameter 22, hole 10, Top Layer to Bottom Layer, 27 vias
v4: diameter 19, hole 8, Top Layer to Bottom Layer, tented both sides, 1 vias

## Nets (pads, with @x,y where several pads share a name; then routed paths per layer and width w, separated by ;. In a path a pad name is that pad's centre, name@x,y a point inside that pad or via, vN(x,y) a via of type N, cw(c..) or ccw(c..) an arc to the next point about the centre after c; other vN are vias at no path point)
3V: C2.2 L1.2 L3.1 R5.2 TP1.1 U1.5 U1.8 U1.9 | length 4073.2
  Top Layer w9: U1.9@1215.3,2262.4 1215.3,2284.84 v1(1225.45,2295) 1234.98,2285.47 U1.8@1234.98,2262.4 ; U1.5@1234.98,2187.6 1234.98,2172.47 1241.45,2166 1241.45,2114.31 L1.2@1260.77,2095
  Top Layer w10: v1(510,1085) R5.2@510,1113.5
  Top Layer w20: v3(1940,3095) 2055,3210 TP1.1@2080,3210
  Signal Layer 2 w20: v1(1225.45,2295) 1390,2295 1400.45,2284.55 v1(1400.45,2145) ; 1330,2300 1330,2485 v3(1940,3095) ; v1@1400.45,2140 1415.45,2155
  Signal Layer 2 w35: v1(1380.45,2130) 1545.45,2130 1595,2080.45 ; 1595,2080 2040,2080
  Bottom Layer w10: v1(510,1085) 875,1085 1400.45,1610.45 v1(1400.45,2115)
  other v1: 2019,2070 2049,2070 2034,2090
6V: C1.2 C3.2 C5.2 C6.2 Q1.1 Q1.2 Q1.5 Q1.6 Q1.8 TP2.1 U1.1 U1.12 U3.12 | length 260.3
  Top Layer w10: 1090,2350 1156.24,2284.21 U1.12@1156.24,2262.4
  Top Layer w15: C5.2@811.42,1322.2 C5.2@825,1308.62 ; C6.2@861.38,1308.62 C6.2@875,1295
  Top Layer w17: U3.12@741.14,1322.2 C5.2@811.42,1322.2
  Top Layer w20: C5.2@825,1308.62 C6.2@861.38,1308.62
ADC_BATT: R1.1 R2.1 U9.24 | length 1566.6
  Top Layer w9: v1(1650,1175) 1650,1110 1715,1045 1855,1045 1916.1,983.9 U9.24@1916.1,974.49
  Top Layer w10: v3(1330,1950) 1445.45,2065.45 R1.1@1445.45,2113.5 R2.1@1500.45,2113.5
  Signal Layer 2 w10: v3(1330,1950) 1330,1495 v1(1650,1175)
ADC_ROTARY: R3.2 U9.27 | length 2124.4
  Top Layer w9: v3(1110,1985) 1110,1935 1495,1550 1495,1075 1590,980 1625,980 1630,985 1830,985 1845,970 1845,925 1860.47,909.53 U9.27@1890.51,909.53
  Top Layer w10: R3.2@673.9,2285 v3(780,2285)
  Bottom Layer w10: v3(780,2285) 810,2285 v3(1110,1985)
DCDC_SW: L2.1 U9.17 | length 222.2
  Top Layer w9: U9.17@2053.9,974.49 2053.9,1058.9 2070,1075 L2.1@2070,1190
EN_BATT: U1.4 U9.23 | length 1636.9
  Top Layer w9: U1.4@1215.3,2187.6 1215.3,2161.16 v4(1217.45,2159) ; v1(1695,1175) 1695,1095 1725,1065 1860,1065 1935.79,989.21 U9.23@1935.79,974.49
  Signal Layer 2 w10: v4(1217.45,2159) 1296.45,2159 1310.45,2145 1310.45,2005 1375,1940.45 1375,1495 v1(1695,1175)
EN_ROTARY: Q2.1@700,2075.32 R12.1 U9.10 | length 2365.5
  Top Layer w9: U9.10@2079.49,830.79 2109.21,830.79 v1(2140,800)
  Top Layer w10: Q2.1@700,2075.32 700,1975 v3(735,1940) ; v3(1159.68,1940.32) v3(1970,1130)
  Bottom Layer w10: v3(735,1940) 735.32,1940.32 v3(1159.68,1940.32) ; v3(1970,1130) 2135,1130 2230,1035 2230,890 v1(2140,800)
GND: BT2.2 C1.1 C2.1 C3.1 C4.1 C6.1 C7.1 C8.2 C9.1 C10.1 C11.2 C12.1 C13.1 C14.2 C15.1 C16.2 C17.1 C18.1 C19.2 C20.1 C21.1 C22.1 C23.1 C24.1 C26.2 C27.2 C28.1 C29.1 C30.2 C31.1 E1.1 J3.3 J3.5 J3.9 J4.2 J4.3 J4.4 J4.5 Q1.3 R2.2 R3.3 R4.1 S1.1 S1.2 S2.1 S2.2 S3.1 S3.2 TP3.1 TP4.1 TP9.1 U1.3 U1.10 U1.11 U1.13@1205.45,2225 U2.2 U3.13 U3.17 U4.B2 U4.C1 U4.D1 U5.1 U5.5 U5.7 U6.2 U7.2 U8.2 U9.33 Y1.2 Y1.4 | length 1428.9
  Top Layer w9: U1.3@1195.61,2187.6 1195.61,2215.16 v2(1205.45,2225)
  Top Layer w10: v3(3700,1575) 3850,1575 ; v3(3710,1875) 3875,1875 3889.53,1889.53 U4.D1@3889.53,1940.32 U4.C1@3869.84,1940.32 ; v3(3710,2015) v3(3850,2015) ; 3720,2270 3815,2270 ; C10.1@3785.31,2335 3785.31,2317.8 U5.5@3806.61,2296.5 ; U5.5@3805,2294.88 3805,2280 3815,2270 ; U2.2@3850,1604.88 3850,1575 ; U4.B2@3850.16,1979.69 v3@3850.16,2014.84 ; 3857.8,2272.8 U5.7@3857.8,2296.5 3857.8,2337.48 C9.1@3860.31,2340 ; U5.1@3883.39,2233.5 3883.39,2266.61 3880,2270 3815,2270 ; C4.1@3889.69,1750 3910,1750 3930,1730 3930,1595 3910,1575 3850,1575
  Top Layer w15: v2(625,1335) 637.8,1347.8 U3.13@741.14,1347.8 ; v3(3850,2015) v3@3850.16,2014.84
  Signal Layer 2 w15: v1@2310,1250 v1(2315,1250)
  Bottom Layer w10: C7.1@3850,1979.68 v3(3850,2015)
  other v1: 1319.99,345 1379.99,345 1439.99,345 1499.99,345 1559.99,345 1619.99,345 1679.99,345 1739.99,345 1799.99,345 1985,345 2045,345 2089.99,345 2149.99,345 1259.99,380 1475,380 1830,380 1870,380 1019.99,385 1079.99,385 1139.99,385 1199.99,385 2199.99,385 2259.99,385 2319.99,385 2379.99,385 2439.99,385 1945,390 2520,400 2615,400 1870,415 1475,420 1945,425 1395,440 2355,445 2440,445 245,450 395,450 545,450 695,450 845,450 995,450 1145,450 1295,450 1595,450 1870,450 1995,450 2060,450 2125,450 2495,450 2645,450 2795,450 2945,450 3095,450 3245,450 3395,450 3545,450 3695,450 3845,450 2275,455 1475,460 1945,460 1710,465 2195,480 2535,480 1870,485 1945,495 1475,500 1395,505 2440,505 1550,515 2360,525 2695,525 2730,525 2765,525 3125,525 3265,525 3300,525 3335,525 1945,530 1995,535 2035,535 2075,535 2115,535 2150,535 1475,540 2275,540 1870,545 3665,545 1710,560 1945,565 2520,565 1395,570 2175,570 1475,580 1870,580 2230,580 2445,580 320,600 470,600 620,600 770,600 920,600 1070,600 1220,600 1370,600 1670,600 1820,600 1945,600 1995,600 2145,600 2420,600 2570,600 3920,600 2320,610 1870,615 1475,620 1395,630 2145,630 2185,630 2225,630 2270,630 2515,640 1870,650 1985,655 2410,655 3665,655 1475,660 1945,660 2145,665 2310,665 2350,670 1395,685 1870,685 1475,700 1515,700 1555,700 1595,700 1635,700 1675,700 1715,700 1800,720 1835,720 1870,720 1735,730 1770,730 1455,745 395,750 545,750 695,750 845,750 995,750 1145,750 1295,750 1600,750 2645,750 2795,750 2945,750 3095,750 3245,750 3395,750 3545,750 2440,755 1540,760 3650,775 2315,780 1590,790 2480,800 1500,815 2310,815 3125,820 2350,825 2680,825 1570,830 2730,835 2755,835 3300,835 3335,835 2215,840 2320,840 1390,850 2345,855 2155,860 2310,865 1570,870 3335,870 2505,875 1500,880 2300,890 320,900 470,900 620,900 920,900 1070,900 1220,900 1370,900 2570,900 3770,900 3920,900 1570,910 2365,915 2505,930 1500,945 1585,945 1770,945 1790,955 1685,960 1560,970 1390,980 2375,985 1530,990 2505,990 1495,1010 2110,1035 2135,1035 395,1050 2345,1050 2645,1050 2795,1050 2945,1050 3095,1050 3245,1050 3395,1050 3545,1050 3845,1050 2110,1060 2135,1060 1645,1065 2265,1070 2320,1105 2365,1105 3505,1125 2265,1130 2825,1155 1830,1165 1745,1175 1780,1175 1535,1180 925,1195 1845,1195 1070,1200 1220,1200 1370,1200 2260,1200 2570,1200 2720,1200 2870,1200 3170,1200 3320,1200 3470,1200 3620,1200 3920,1200 945,1210 1410,1210 1705,1225 1810,1225 925,1230 1535,1230 950,1235 1945,1235 2410,1235 2470,1235 1660,1250 1750,1250 1970,1250 2565,1250 2590,1250 1915,1260 1990,1270 1775,1285 1930,1290 1965,1290 1845,1300 2165,1305 1420,1310 1695,1310 1900,1325 2100,1330 2275,1340 995,1350 1295,1350 2195,1350 2345,1350 2495,1350 2645,1350 2795,1350 2945,1350 3095,1350 3245,1350 3395,1350 3545,1350 3695,1350 1900,1380 2085,1380 1765,1385 2175,1385 1535,1395 2305,1395 1970,1400 795,1485 825,1485 340,1500 365,1500 390,1500 415,1500 440,1500 620,1500 1220,1500 1670,1500 1820,1500 1970,1500 2120,1500 2420,1500 2570,1500 2720,1500 2870,1500 3020,1500 3170,1500 3470,1500 1975,1533 2080,1540 245,1650 395,1650 545,1650 695,1650 845,1650 1295,1650 1895,1650 2195,1650 2345,1650 2495,1650 2795,1650 2945,1650 3395,1650 3545,1650 470,1800 620,1800 770,1800 1520,1800 1820,1800 1970,1800 2120,1800 2420,1800 2570,1800 2720,1800 2870,1800 3020,1800 3170,1800 3320,1800 3470,1800 545,1950 1445,1950 1595,1950 1745,1950 2645,1950 2795,1950 2945,1950 3095,1950 3245,1950 3395,1950 3580,2045 470,2100 620,2100 2120,2100 2420,2100 2570,2100 2720,2100 2870,2100 3020,2100 3170,2100 3320,2100 3470,2100 1500.45,2210 1135.45,2225 1275.45,2225 545,2250 1445,2250 1745,2250 1895,2250 2045,2250 3095,2250 3245,2250 3395,2250 3545,2250 1070.45,2265 1100.45,2265 1300.45,2265 1335.45,2265 1365.45,2265 1085.45,2290 1110,2290 1185.45,2295 470,2400 770,2400 1220,2400 1370,2400 1520,2400 1670,2400 1820,2400 1970,2400 2120,2400 2270,2400 2420,2400 2720,2400 2870,2400 3020,2400 3320,2400 245,2550 395,2550 545,2550 695,2550 845,2550 995,2550 1445,2550 1595,2550 1745,2550 1895,2550 2045,2550 2195,2550 2345,2550 2495,2550 2645,2550 2945,2550 3095,2550 3245,2550 3395,2550 3695,2550 3845,2550 3580,2585 620,2700 770,2700 920,2700 2270,2700 2420,2700 3020,2700 3320,2700 3470,2700 3770,2700 3920,2700 245,2850 395,2850 545,2850 695,2850 845,2850 2345,2850 2495,2850 2795,2850 2945,2850 3245,2850 3395,2850 3695,2850 3845,2850 1710,2930 1715,2970 1675,2995 1750,2995 320,3000 470,3000 620,3000 770,3000 920,3000 1970,3000 2120,3000 2270,3000 2420,3000 2570,3000 2720,3000 2870,3000 3020,3000 3770,3000 3920,3000 1675,3035 1750,3035 1675,3075 1750,3075 1710,3100 3580,3125 1720,3140 395,3150 545,3150 695,3150 845,3150 995,3150 1295,3150 1895,3150 2195,3150 2345,3150 2645,3150 2795,3150 2945,3150 3245,3150 3395,3150 620,3300 770,3300 920,3300 1070,3300 1220,3300 1370,3300 1520,3300 1670,3300 1820,3300 1970,3300 2120,3300 2270,3300 2420,3300 2570,3300 2720,3300 2870,3300 3020,3300 3170,3300 3320,3300 3470,3300
  other v2: 1930,825 1965,825 2005,825 2040,825 1930,860 1965,860 2005,860 2040,860 1930,900 1965,900 2005,900 2040,900 1930,935 1965,935 2005,935 2040,935 2945,1200 603.35,1313.35 646.65,1313.35 603.35,1356.65 646.65,1356.65 1175.45,2225 1235.45,2225
  other v3: 3710,2275
I2C_SCL: R10.1 TP6.1 U2.6 U4.A1 U5.4 U9.7 | length 4170.9
  Top Layer w9: U9.7@2034.21,785.51 2034.21,772.79 2050,757 v1(2050,735)
  Top Layer w10: v3(3640,1390) 3640,1645 ; 3685.12,1715.12 U2.6@3810.63,1715.12 ; TP6.1@3770,1150 3770,1041.5 R10.1@3771.5,1040 ; TP6.1@3790,1160 v3(3790,1215) ; U5.4@3805.12,2235 U5.4@3806.61,2233.5 3718.5,2233.5 3640.25,2155.25 3640.25,1789.72 3630,1779.47 3630,1655 3640,1645 ; U4.A1@3830.47,1940.32 3720.31,1940.32 3685,1905 3685,1690 3640,1645
  Signal Layer 2 w10: v1(2050,735) 2095,690 2335,690 2475,830 2475,1055 2515,1095 3225,1095 3280,1150 3710,1150 3775,1215 v3(3790,1215)
  Bottom Layer w10: v3(3640,1390) 3640,1255 3680,1215 v3(3790,1215)
I2C_SDA: R9.1 TP5.1 U2.1 U4.A2 U5.3 U9.6 | length 3675.9
  Top Layer w9: U9.6@2014.53,785.51 2014.53,760.47 v1@2025,750
  Top Layer w10: v3(3660,1715) 3660,2140 3725,2205 3825,2205 3832.2,2212.2 U5.3@3832.2,2233.5 ; 3660.31,1979.69 U4.A2@3830.47,1979.69 ; v3(3765,1255) TP5.1@3765,1402.13 ; TP5.1@3800,1385 3665,1520 v3(3665,1575) 3694.88,1604.88 U2.1@3810.63,1604.88
  Signal Layer 2 w10: v1(2023,750) 2033,760 2065,760 2115,710 2320,710 2450,840 2450,1065 2510,1125 3215,1125 3260,1170 3680,1170 v3(3765,1255) ; v3(3660,1715) 3660,1580 v3(3665,1575)
IN1: TP7.1 U3.9 U3.16 U9.21 | length 2507.2
  Top Layer w9: v1(1760,1125) 1780,1105 1870,1105 1975.16,999.84 U9.21@1975.16,974.49
  Top Layer w10: TP7.1@150,760 v3(150,875) ; U3.16@741.14,1424.57 779.57,1424.57 v1(780,1425)
  Top Layer w15: U3.9@741.43,1245 v1(780,1245)
  Signal Layer 2 w10: v3(150,875) 450,1175 665,1175 735,1245 v1(780,1245) ; v1(780,1425) v1(780,1245) ; v1(1760,1125) 1735,1150 825,1150 780,1195 v1(780,1245)
IN2: TP8.1 U3.10 U3.15 U9.22 | length 2489
  Top Layer w9: v1(1725,1125) 1725,1110 1750,1085 1865,1085 1955.47,994.53 U9.22@1955.47,974.49
  Top Layer w10: TP8.1@150,980 v3(150,1065) ; v1(550,1150) v1@550,1210 ; v1(701,1398) 701.98,1398.98 U3.15@741.14,1398.98
  Top Layer w15: v1@704.02,1271.02 U3.10@741.14,1271.02
  Signal Layer 2 w10: v3(150,1065) 290,1205 v1(550,1205) 638,1205 704.02,1271.02 701,1274.05 v1(701,1398) ; v1(550,1150) 575,1125 v1(1725,1125)
  other v1: 700.02,1271.02
JTAG_TCK: J3.4 U7.1 U9.14 | length 1971.1
  Top Layer w9: U9.14@2079.49,909.53 2109.53,909.53 2160,960 v1(2270,960)
  Top Layer w10: U7.1@3714.69,626 J3.4@3803,626
  Bottom Layer w10: v1(2270,960) 2370,960 2704,626 J3.4@3803,626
